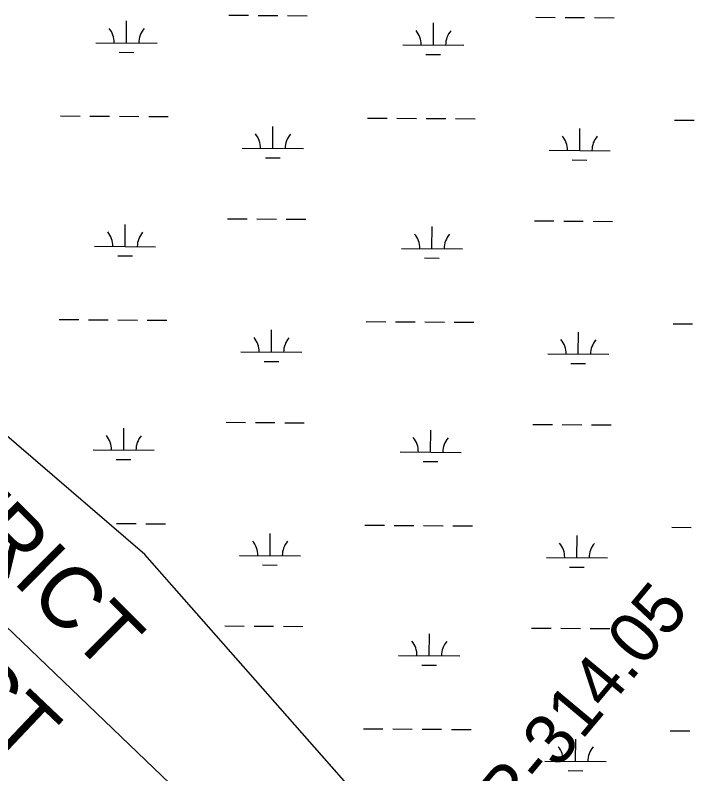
# Model space of a CAD drawing. Extents: x 3172231 to 3210228, y 940198 to 965780.
# Drawn here: x 3194853 to 3195968, y 949521 to 950760 of the extents above; entities that cross this region are included whole.
import ezdxf

# ---------------------------------------------------------------- set-up
doc = ezdxf.new("R2010")
doc.units = 0
for name, color, linetype in [('V-RIVR-RANG-IDEN', 7, 'Continuous'), ('V-TOPO-BNDY', 7, 'Continuous'), ('V-TOPO-GNAM-IDEN', 7, 'Continuous'), ('V-WETL-SWMP', 7, 'Continuous')]:
    doc.layers.add(name, color=color, linetype=linetype)

msp = doc.modelspace()

# ---------------------------------------------------------------- linework, layer by layer
at = {"layer": 'V-TOPO-BNDY'}
msp.add_line((3194332.024, 950245.511), (3197716.878, 947007.215), dxfattribs=at)
at = {"layer": 'V-WETL-SWMP'}
for p, q in [((3195202.314, 950760.24), (3195234.313, 950760.022)), ((3195250.313, 950759.913), (3195282.312, 950759.695)), ((3195298.312, 950759.586), (3195330.311, 950759.368)), ((3195034.938, 950714.948), (3195035.183, 950750.947)), ((3195536.834, 950711.532), (3195537.079, 950747.531)), ((3195704.21, 950756.823), (3195736.21, 950756.605)), ((3195752.209, 950756.497), (3195784.208, 950756.279)), ((3195800.208, 950756.17), (3195832.207, 950755.952)), ((3194984.939, 950715.288), (3195084.937, 950714.608)), ((3195486.835, 950711.872), (3195586.833, 950711.191)), ((3195022.833, 950699.599), (3195046.832, 950699.436)), ((3195524.729, 950696.183), (3195548.729, 950696.019)), ((3194927.279, 950595.607), (3194959.278, 950595.389)), ((3194975.278, 950595.28), (3195007.277, 950595.063)), ((3195023.277, 950594.954), (3195055.276, 950594.736)), ((3195071.276, 950594.627), (3195103.275, 950594.409)), ((3195429.175, 950592.191), (3195461.175, 950591.973)), ((3195477.174, 950591.864), (3195509.173, 950591.646)), ((3195525.173, 950591.537), (3195557.172, 950591.319)), ((3195573.172, 950591.21), (3195605.171, 950590.993)), ((3195931.072, 950588.774), (3195963.071, 950588.556)), ((3195274.241, 950542.502), (3195274.486, 950578.501)), ((3195776.138, 950539.086), (3195776.383, 950575.085)), ((3195224.243, 950542.842), (3195324.24, 950542.162)), ((3195726.139, 950539.426), (3195826.137, 950538.745)), ((3195262.137, 950527.153), (3195286.136, 950526.99)), ((3195764.033, 950523.737), (3195788.032, 950523.573)), ((3195200.049, 950427.572), (3195232.049, 950427.355)), ((3195248.048, 950427.246), (3195280.048, 950427.028)), ((3195296.047, 950426.919), (3195328.046, 950426.701)), ((3195032.673, 950382.281), (3195032.918, 950418.28)), ((3195534.57, 950378.864), (3195534.815, 950414.863)), ((3195701.946, 950424.156), (3195733.945, 950423.938)), ((3195749.945, 950423.829), (3195781.944, 950423.611)), ((3195797.944, 950423.503), (3195829.943, 950423.285)), ((3194982.674, 950382.621), (3195082.672, 950381.94)), ((3195484.571, 950379.205), (3195584.568, 950378.524)), ((3195020.568, 950366.932), (3195044.568, 950366.768)), ((3195522.465, 950363.515), (3195546.464, 950363.352)), ((3194925.014, 950262.94), (3194957.014, 950262.722)), ((3194973.013, 950262.613), (3195005.013, 950262.395)), ((3195021.012, 950262.286), (3195053.011, 950262.069)), ((3195069.011, 950261.96), (3195101.01, 950261.742)), ((3195426.911, 950259.523), (3195458.91, 950259.305)), ((3195474.91, 950259.197), (3195506.909, 950258.979)), ((3195522.909, 950258.87), (3195554.908, 950258.652)), ((3195570.907, 950258.543), (3195602.907, 950258.325)), ((3195928.807, 950256.107), (3195960.806, 950255.889)), ((3195271.977, 950209.835), (3195272.222, 950245.834)), ((3195773.873, 950206.418), (3195774.118, 950242.417)), ((3195221.978, 950210.175), (3195321.976, 950209.494)), ((3195723.874, 950206.759), (3195823.872, 950206.078)), ((3195259.872, 950194.486), (3195283.872, 950194.322)), ((3195761.769, 950191.069), (3195785.768, 950190.906)), ((3195064.919, 949879.193), (3194806.172, 950101.067)), ((3195197.785, 950094.905), (3195229.784, 950094.687)), ((3195245.784, 950094.578), (3195277.783, 950094.361)), ((3195293.783, 950094.252), (3195325.782, 950094.034)), ((3195699.681, 950091.489), (3195731.681, 950091.271)), ((3195747.68, 950091.162), (3195779.679, 950090.944)), ((3195795.679, 950090.835), (3195827.678, 950090.617)), ((3195030.409, 950049.613), (3195030.654, 950085.613)), ((3195532.305, 950046.197), (3195532.55, 950082.196)), ((3194980.41, 950049.954), (3195080.408, 950049.273)), ((3195482.306, 950046.537), (3195582.304, 950045.857)), ((3195018.304, 950034.264), (3195042.303, 950034.101)), ((3195520.2, 950030.848), (3195544.2, 950030.685)), ((3195018.748, 949929.619), (3195050.747, 949929.401)), ((3195066.747, 949929.292), (3195098.746, 949929.074)), ((3195424.646, 949926.856), (3195456.645, 949926.638)), ((3195472.645, 949926.529), (3195504.644, 949926.311)), ((3195520.644, 949926.203), (3195552.643, 949925.985)), ((3195568.643, 949925.876), (3195600.642, 949925.658)), ((3195926.543, 949923.44), (3195958.542, 949923.222)), ((3195269.712, 949877.168), (3195269.957, 949913.167)), ((3195771.609, 949873.751), (3195771.854, 949909.75)), ((3195619.376, 949250.55), (3195064.919, 949879.193)), ((3195219.714, 949877.508), (3195319.711, 949876.827)), ((3195721.61, 949874.091), (3195821.608, 949873.411)), ((3195257.608, 949861.819), (3195281.607, 949861.655)), ((3195759.504, 949858.402), (3195783.503, 949858.239)), ((3195195.52, 949762.238), (3195227.52, 949762.02)), ((3195243.519, 949761.911), (3195275.519, 949761.693)), ((3195291.518, 949761.584), (3195323.517, 949761.367)), ((3195697.417, 949758.821), (3195729.416, 949758.604)), ((3195745.416, 949758.495), (3195777.415, 949758.277)), ((3195793.415, 949758.168), (3195825.414, 949757.95)), ((3195530.041, 949713.53), (3195530.286, 949749.529)), ((3195480.042, 949713.87), (3195580.039, 949713.189)), ((3195517.936, 949698.181), (3195541.935, 949698.017)), ((3195422.382, 949594.189), (3195454.381, 949593.971)), ((3195470.381, 949593.862), (3195502.38, 949593.644)), ((3195518.379, 949593.535), (3195550.379, 949593.317)), ((3195566.378, 949593.209), (3195598.378, 949592.991)), ((3195924.278, 949590.772), (3195956.277, 949590.554)), ((3195769.344, 949541.084), (3195769.589, 949577.083)), ((3195719.345, 949541.424), (3195819.343, 949540.743)), ((3195757.24, 949525.735), (3195781.239, 949525.571))]:
    msp.add_line(p, q, dxfattribs=at)
for centre, start, end in [((3194979.699, 950715.799), 358.838165, 40.381824), ((3195090.183, 950715.047), 138.838162, 180.381821), ((3195481.596, 950712.382), 358.838165, 40.381824), ((3195592.079, 950711.63), 138.838162, 180.381821), ((3195219.003, 950543.353), 358.838165, 40.381824), ((3195329.486, 950542.601), 138.838162, 180.381821), ((3195720.899, 950539.936), 358.838165, 40.381824), ((3195831.383, 950539.184), 138.838162, 180.381821), ((3194977.435, 950383.132), 358.838165, 40.381824), ((3195087.918, 950382.379), 138.838162, 180.381821), ((3195479.331, 950379.715), 358.838165, 40.381824), ((3195589.814, 950378.963), 138.838162, 180.381821), ((3195216.739, 950210.686), 358.838165, 40.381824), ((3195327.222, 950209.934), 138.838162, 180.381821), ((3195718.635, 950207.269), 358.838165, 40.381824), ((3195829.118, 950206.517), 138.838162, 180.381821), ((3194975.17, 950050.464), 358.838165, 40.381824), ((3195085.654, 950049.712), 138.838162, 180.381821), ((3195477.067, 950047.048), 358.838165, 40.381824), ((3195587.55, 950046.296), 138.838162, 180.381821), ((3195214.474, 949878.018), 358.838165, 40.381824), ((3195324.957, 949877.266), 138.838162, 180.381821), ((3195716.37, 949874.602), 358.838165, 40.381824), ((3195826.854, 949873.85), 138.838162, 180.381821), ((3195474.802, 949714.38), 358.838165, 40.381824), ((3195585.285, 949713.628), 138.838162, 180.381821), ((3195714.106, 949541.935), 358.838165, 40.381824), ((3195824.589, 949541.182), 138.838162, 180.381821)]:
    msp.add_arc(centre, 35.246, start, end, dxfattribs=at)

# ---------------------------------------------------------------- texts
at = {"layer": 'V-RIVR-RANG-IDEN'}
msp.add_text('R-314.05', height=82.9998, rotation=50.165881, dxfattribs=at).set_placement((3195664.87, 949437.019))
at = {"layer": 'V-TOPO-GNAM-IDEN'}
for rotation, p in [(315.174813, (3194562.298, 950118.02)), (316.502046, (3194418.095, 949958.13))]:
    msp.add_text('DISTRICT', height=99.9998, rotation=rotation, dxfattribs=at).set_placement(p)

doc.saveas('drawing.dxf')
